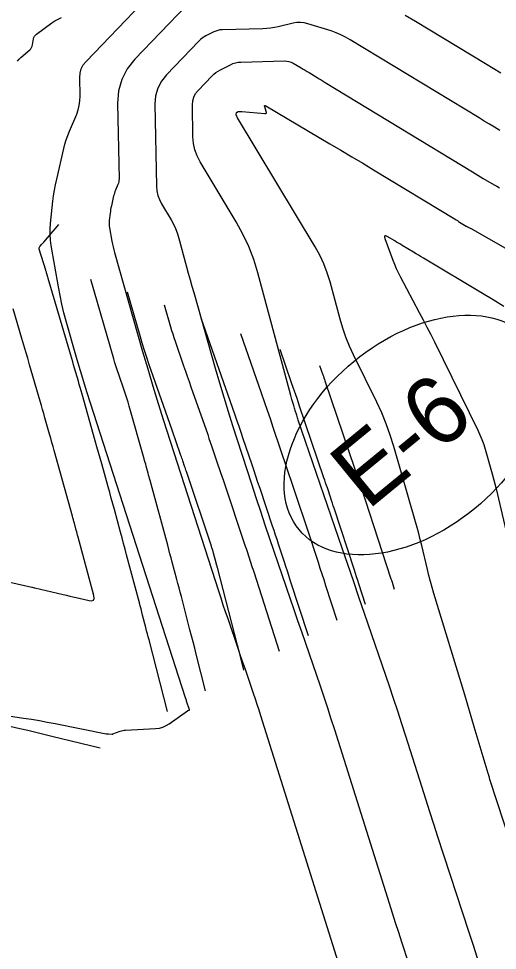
# Model space of a CAD drawing. Extents: x 1005228 to 1008882, y 1883389 to 1885754.
# Drawn here: x 1008220.2 to 1008264.2, y 1884267.3 to 1884352.9 of the extents above; entities that cross this region are included whole.
import ezdxf

# ---------------------------------------------------------------- set-up
doc = ezdxf.new("R2010")
doc.units = 0
for name, color, linetype in [('ATDIMS', 7, 'Continuous'), ('C-ANNO-NOTE', 7, 'Continuous'), ('R_Erosion', 7, 'Continuous'), ('S_BRIDGE', 7, 'Continuous'), ('TSOBSTACLE', 7, 'Continuous')]:
    doc.layers.add(name, color=color, linetype=linetype)

msp = doc.modelspace()

# ---------------------------------------------------------------- linework, layer by layer
at = {"layer": 'ATDIMS'}
for points in [[(1008217.624, 1884301.505), (1008221.421, 1884300.64), (1008221.459, 1884300.631), (1008221.546, 1884300.612), (1008221.646, 1884300.59), (1008221.662, 1884300.587), (1008221.679, 1884300.583), (1008221.695, 1884300.579), (1008221.712, 1884300.575), (1008224.325, 1884299.96), (1008224.621, 1884299.891), (1008224.917, 1884299.822), (1008225.213, 1884299.753), (1008225.508, 1884299.684), (1008226.692, 1884299.41), (1008226.941, 1884299.387), (1008227.097, 1884299.454), (1008227.159, 1884299.612), (1008227.127, 1884299.86), (1008225.689, 1884305.243), (1008225.646, 1884305.402), (1008225.604, 1884305.562), (1008225.561, 1884305.721), (1008225.517, 1884305.881), (1008225.345, 1884306.519), (1008225.301, 1884306.678), (1008225.258, 1884306.838), (1008225.214, 1884306.997), (1008225.169, 1884307.156), (1008223.489, 1884313.184), (1008223.383, 1884313.562), (1008223.277, 1884313.94), (1008223.171, 1884314.317), (1008223.064, 1884314.695), (1008222.637, 1884316.206), (1008222.53, 1884316.583), (1008222.422, 1884316.961), (1008222.314, 1884317.338), (1008222.205, 1884317.715), (1008221.23, 1884321.065), (1008221.055, 1884321.666), (1008220.879, 1884322.267), (1008220.703, 1884322.868), (1008220.526, 1884323.469), (1008219.72, 1884326.205)], [(1008236.97, 1884325.388), (1008240.052, 1884316.574), (1008240.25, 1884316.004), (1008240.448, 1884315.434), (1008240.643, 1884314.863), (1008240.838, 1884314.292), (1008241.613, 1884312.007), (1008241.806, 1884311.436), (1008242, 1884310.864), (1008242.192, 1884310.292), (1008242.384, 1884309.72), (1008243.539, 1884306.279), (1008243.677, 1884305.867), (1008243.814, 1884305.455), (1008243.95, 1884305.043), (1008244.086, 1884304.63), (1008244.626, 1884302.979), (1008244.76, 1884302.566), (1008244.895, 1884302.153), (1008245.029, 1884301.74), (1008245.163, 1884301.327), (1008246.825, 1884296.198)]]:
    msp.add_lwpolyline(points, dxfattribs=at)
at = {"layer": 'C-ANNO-NOTE'}
for points in [[(1008216.682, 1884289.232), (1008220.679, 1884288.624), (1008221.405, 1884288.509), (1008222.13, 1884288.386), (1008222.853, 1884288.254), (1008223.575, 1884288.115), (1008228.269, 1884287.178), (1008228.324, 1884287.169), (1008228.38, 1884287.162), (1008228.435, 1884287.157), (1008228.491, 1884287.155), (1008228.814, 1884287.152), (1008228.84, 1884287.152), (1008228.866, 1884287.152), (1008228.872, 1884287.152), (1008228.878, 1884287.153), (1008228.885, 1884287.155), (1008228.891, 1884287.157), (1008229.567, 1884287.414), (1008229.683, 1884287.453), (1008229.801, 1884287.483), (1008229.92, 1884287.504), (1008230.042, 1884287.515), (1008232.817, 1884287.662), (1008233.155, 1884287.704), (1008233.477, 1884287.79), (1008233.783, 1884287.923), (1008234.072, 1884288.101), (1008235.73, 1884289.282), (1008235.747, 1884289.293), (1008235.765, 1884289.302), (1008235.785, 1884289.309), (1008235.805, 1884289.314), (1008235.887, 1884289.329), (1008235.905, 1884289.334), (1008235.915, 1884289.344), (1008235.919, 1884289.358), (1008235.916, 1884289.376), (1008235.664, 1884290.175), (1008235.66, 1884290.188), (1008235.656, 1884290.201), (1008235.651, 1884290.215), (1008235.647, 1884290.228), (1008235.585, 1884290.408), (1008235.579, 1884290.425), (1008235.574, 1884290.442), (1008235.568, 1884290.459), (1008235.563, 1884290.475), (1008226.535, 1884318.49), (1008226.278, 1884319.298), (1008226.029, 1884320.108), (1008225.786, 1884320.92), (1008225.55, 1884321.734), (1008224.602, 1884325.062), (1008224.389, 1884325.845), (1008224.198, 1884326.633), (1008224.027, 1884327.426), (1008223.878, 1884328.224), (1008223.218, 1884332.014), (1008223.148, 1884332.52), (1008223.114, 1884333.027), (1008223.116, 1884333.535), (1008223.153, 1884334.045), (1008223.377, 1884336.085), (1008223.44, 1884336.594), (1008223.518, 1884337.1), (1008223.612, 1884337.604), (1008223.72, 1884338.105), (1008224.371, 1884340.915), (1008224.475, 1884341.326), (1008224.598, 1884341.732), (1008224.737, 1884342.131), (1008224.894, 1884342.525), (1008225.557, 1884344.09), (1008225.701, 1884344.485), (1008225.801, 1884344.889), (1008225.858, 1884345.301), (1008225.872, 1884345.721), (1008225.84, 1884347.446), (1008225.87, 1884347.86), (1008225.977, 1884348.244), (1008226.16, 1884348.598), (1008226.419, 1884348.923), (1008234.44, 1884357.265)], [(1008235.618, 1884354.034), (1008230.912, 1884349.139), (1008230.199, 1884348.247), (1008229.696, 1884347.272), (1008229.402, 1884346.214), (1008229.319, 1884345.075), (1008229.448, 1884338.143), (1008229.444, 1884338.005), (1008229.425, 1884337.87), (1008229.392, 1884337.738), (1008229.345, 1884337.608), (1008229.128, 1884337.096), (1008229.077, 1884336.967), (1008229.031, 1884336.836), (1008228.991, 1884336.703), (1008228.957, 1884336.569), (1008228.744, 1884335.648), (1008228.708, 1884335.484), (1008228.677, 1884335.319), (1008228.652, 1884335.154), (1008228.631, 1884334.987), (1008228.558, 1884334.319), (1008228.546, 1884334.152), (1008228.545, 1884333.985), (1008228.556, 1884333.819), (1008228.579, 1884333.653), (1008228.795, 1884332.412), (1008228.844, 1884332.151), (1008228.9, 1884331.891), (1008228.963, 1884331.633), (1008229.032, 1884331.377), (1008231.621, 1884322.296), (1008232.083, 1884320.699), (1008232.559, 1884319.107), (1008233.049, 1884317.518), (1008233.552, 1884315.934), (1008238.588, 1884300.307), (1008238.795, 1884299.668), (1008239.006, 1884299.03), (1008239.219, 1884298.393), (1008239.436, 1884297.757), (1008240.394, 1884294.959), (1008240.568, 1884294.452), (1008240.742, 1884293.945), (1008240.916, 1884293.437), (1008241.09, 1884292.93), (1008241.785, 1884290.901), (1008241.958, 1884290.393), (1008242.127, 1884289.885), (1008242.293, 1884289.375), (1008242.456, 1884288.864), (1008251.629, 1884259.753)], [(1008220.119, 1884348.952), (1008220.271, 1884349.119), (1008220.435, 1884349.276), (1008221.25, 1884350.001), (1008221.343, 1884350.098), (1008221.416, 1884350.206), (1008221.469, 1884350.325), (1008221.503, 1884350.455), (1008221.596, 1884350.998), (1008221.63, 1884351.127), (1008221.687, 1884351.242), (1008221.765, 1884351.343), (1008221.866, 1884351.431), (1008223.284, 1884352.459), (1008223.564, 1884352.645), (1008223.855, 1884352.809), (1008224.158, 1884352.949)], [(1008264.549, 1884347.843), (1008263.839, 1884348.269), (1008263.13, 1884348.698), (1008256.701, 1884352.599), (1008255.761, 1884353.132)], [(1008262.504, 1884266.257), (1008262.054, 1884267.635), (1008261.604, 1884269.012), (1008258.755, 1884277.711), (1008258.379, 1884278.863), (1008258.007, 1884280.016), (1008257.638, 1884281.17), (1008257.272, 1884282.325), (1008255.816, 1884286.946), (1008255.448, 1884288.101), (1008255.073, 1884289.252), (1008254.691, 1884290.402), (1008254.302, 1884291.549), (1008252.013, 1884298.228), (1008251.5, 1884299.723), (1008250.988, 1884301.218), (1008250.475, 1884302.713), (1008249.963, 1884304.208), (1008245.929, 1884315.98), (1008245.891, 1884316.091), (1008245.854, 1884316.201), (1008245.818, 1884316.312), (1008245.782, 1884316.423), (1008245.639, 1884316.866), (1008245.603, 1884316.977), (1008245.569, 1884317.089), (1008245.536, 1884317.2), (1008245.503, 1884317.312), (1008245.372, 1884317.773), (1008245.34, 1884317.887), (1008245.308, 1884318.001), (1008245.276, 1884318.115), (1008245.245, 1884318.23), (1008242.209, 1884329.525), (1008241.836, 1884330.743), (1008241.381, 1884331.927), (1008240.844, 1884333.076), (1008240.226, 1884334.19), (1008236.905, 1884339.714), (1008236.625, 1884340.253), (1008236.422, 1884340.815), (1008236.296, 1884341.398), (1008236.246, 1884342.003), (1008236.192, 1884344.926), (1008236.219, 1884345.3), (1008236.316, 1884345.647), (1008236.481, 1884345.967), (1008236.715, 1884346.26), (1008237.975, 1884347.571), (1008238.158, 1884347.745), (1008238.353, 1884347.903), (1008238.56, 1884348.044), (1008238.781, 1884348.168), (1008239.688, 1884348.628), (1008239.918, 1884348.73), (1008240.155, 1884348.804), (1008240.399, 1884348.852), (1008240.65, 1884348.872), (1008244.654, 1884348.973), (1008244.863, 1884348.964), (1008245.065, 1884348.927), (1008245.259, 1884348.861), (1008245.446, 1884348.767), (1008246.179, 1884348.334), (1008246.363, 1884348.225), (1008246.546, 1884348.116), (1008246.728, 1884348.007), (1008246.911, 1884347.897), (1008247.651, 1884347.448), (1008247.836, 1884347.337), (1008248.02, 1884347.225), (1008248.204, 1884347.114), (1008248.388, 1884347.002), (1008261.947, 1884338.773), (1008262.193, 1884338.625), (1008262.44, 1884338.477), (1008262.686, 1884338.33), (1008262.933, 1884338.183), (1008263.923, 1884337.599), (1008264.172, 1884337.456), (1008264.423, 1884337.318)], [(1008266.771, 1884273.092), (1008263.539, 1884282.961), (1008263.525, 1884283.007), (1008263.512, 1884283.053), (1008263.499, 1884283.099), (1008263.488, 1884283.145), (1008263.444, 1884283.331), (1008263.432, 1884283.378), (1008263.42, 1884283.424), (1008263.408, 1884283.47), (1008263.394, 1884283.516), (1008262.106, 1884287.815), (1008261.886, 1884288.546), (1008261.666, 1884289.278), (1008261.444, 1884290.009), (1008261.222, 1884290.74), (1008258.378, 1884300.067), (1008258.217, 1884300.61), (1008258.065, 1884301.155), (1008257.922, 1884301.704), (1008257.788, 1884302.254), (1008257.271, 1884304.461), (1008257.138, 1884305.012), (1008256.999, 1884305.561), (1008256.852, 1884306.108), (1008256.699, 1884306.653), (1008254.712, 1884313.56), (1008254.385, 1884314.608), (1008254.013, 1884315.638), (1008253.596, 1884316.65), (1008253.133, 1884317.645), (1008250.999, 1884321.979), (1008250.629, 1884322.778), (1008250.3, 1884323.592), (1008250.011, 1884324.421), (1008249.762, 1884325.265), (1008248.846, 1884328.671), (1008248.589, 1884329.51), (1008248.275, 1884330.326), (1008247.906, 1884331.118), (1008247.48, 1884331.885), (1008240.354, 1884343.737), (1008240.227, 1884344.025), (1008240.247, 1884344.222), (1008240.415, 1884344.326), (1008240.73, 1884344.338), (1008242.848, 1884344.152), (1008242.938, 1884344.156), (1008242.991, 1884344.188), (1008243.008, 1884344.248), (1008242.989, 1884344.336), (1008242.841, 1884344.741), (1008242.821, 1884344.823), (1008242.832, 1884344.866), (1008242.877, 1884344.87), (1008242.953, 1884344.834), (1008248.824, 1884341.367), (1008249.833, 1884340.77), (1008250.84, 1884340.17), (1008251.846, 1884339.567), (1008252.849, 1884338.961), (1008260.34, 1884334.427), (1008260.445, 1884334.364), (1008260.549, 1884334.301), (1008260.654, 1884334.237), (1008260.758, 1884334.174), (1008261.356, 1884333.811), (1008261.385, 1884333.794), (1008261.413, 1884333.777), (1008261.471, 1884333.743), (1008261.485, 1884333.735), (1008261.5, 1884333.727), (1008261.515, 1884333.719), (1008261.529, 1884333.712), (1008261.776, 1884333.592), (1008261.822, 1884333.569), (1008261.867, 1884333.546), (1008261.912, 1884333.522), (1008261.957, 1884333.497), (1008279.696, 1884323.358)], [(1008264.806, 1884326.427), (1008263.83, 1884327.016), (1008262.852, 1884327.603), (1008257.444, 1884330.842), (1008257.213, 1884330.98), (1008256.983, 1884331.119), (1008256.752, 1884331.258), (1008256.522, 1884331.397), (1008255.484, 1884332.025), (1008255.312, 1884332.129), (1008255.14, 1884332.232), (1008254.968, 1884332.335), (1008254.795, 1884332.437), (1008254.104, 1884332.845), (1008253.961, 1884332.911), (1008253.879, 1884332.904), (1008253.857, 1884332.824), (1008253.896, 1884332.672), (1008254.619, 1884330.688), (1008254.769, 1884330.297), (1008254.933, 1884329.913), (1008255.11, 1884329.534), (1008255.3, 1884329.161), (1008257.049, 1884325.879), (1008257.404, 1884325.208), (1008257.753, 1884324.533), (1008258.096, 1884323.856), (1008258.434, 1884323.176), (1008262.429, 1884315.064), (1008262.628, 1884314.636), (1008262.807, 1884314.201), (1008262.967, 1884313.758), (1008263.108, 1884313.308), (1008263.63, 1884311.492), (1008263.758, 1884311.037), (1008263.88, 1884310.58), (1008263.997, 1884310.123), (1008264.107, 1884309.663), (1008266.588, 1884299.083)]]:
    msp.add_lwpolyline(points, dxfattribs=at)
at = {"layer": 'R_Erosion'}
msp.add_ellipse((1008256.584, 1884314.613), major_axis=(10.591, 8.686), ratio=0.638788, dxfattribs=at)
at = {"layer": 'S_BRIDGE'}
msp.add_lwpolyline([(1008264.453, 1884342.59), (1008263.973, 1884342.874), (1008263.494, 1884343.16), (1008263.016, 1884343.447), (1008262.539, 1884343.736), (1008250.702, 1884350.919), (1008250.279, 1884351.159), (1008249.843, 1884351.373), (1008249.395, 1884351.56), (1008248.936, 1884351.721), (1008246.817, 1884352.393), (1008246.479, 1884352.477), (1008246.139, 1884352.513), (1008245.797, 1884352.501), (1008245.453, 1884352.442), (1008244.076, 1884352.111), (1008243.731, 1884352.037), (1008243.383, 1884351.982), (1008243.032, 1884351.946), (1008242.679, 1884351.927), (1008238.915, 1884351.832), (1008238.716, 1884351.817), (1008238.523, 1884351.779), (1008238.335, 1884351.72), (1008238.153, 1884351.64), (1008237.435, 1884351.275), (1008237.26, 1884351.177), (1008237.096, 1884351.065), (1008236.941, 1884350.941), (1008236.797, 1884350.802), (1008233.814, 1884347.7), (1008233.34, 1884347.107), (1008233.006, 1884346.459), (1008232.811, 1884345.757), (1008232.756, 1884345), (1008232.896, 1884337.462), (1008232.931, 1884337.036), (1008233.02, 1884336.625), (1008233.163, 1884336.23), (1008233.359, 1884335.851), (1008234.254, 1884334.363), (1008234.463, 1884333.985), (1008234.645, 1884333.596), (1008234.8, 1884333.195), (1008234.926, 1884332.781), (1008235.658, 1884330.06), (1008235.818, 1884329.468), (1008235.981, 1884328.875), (1008236.146, 1884328.284), (1008236.313, 1884327.693), (1008238.295, 1884320.74), (1008238.678, 1884319.418), (1008239.072, 1884318.1), (1008239.477, 1884316.785), (1008239.894, 1884315.474), (1008241.613, 1884310.138), (1008242.023, 1884308.877), (1008242.438, 1884307.618), (1008242.859, 1884306.361), (1008243.286, 1884305.106), (1008245.179, 1884299.584), (1008245.522, 1884298.582), (1008245.865, 1884297.581), (1008246.208, 1884296.58), (1008246.551, 1884295.579), (1008247.924, 1884291.574), (1008248.264, 1884290.572), (1008248.598, 1884289.568), (1008248.925, 1884288.561), (1008249.247, 1884287.553), (1008254.271, 1884271.609), (1008254.553, 1884270.72), (1008254.837, 1884269.832), (1008255.123, 1884268.945), (1008255.412, 1884268.059), (1008256.688, 1884264.162)], dxfattribs=at)
at = {"layer": 'TSOBSTACLE'}
for points in [[(1008233.89, 1884289.218), (1008232.209, 1884295.79), (1008232.136, 1884296.075), (1008232.062, 1884296.36), (1008231.989, 1884296.645), (1008231.915, 1884296.93), (1008231.619, 1884298.07), (1008231.545, 1884298.355), (1008231.47, 1884298.639), (1008231.395, 1884298.924), (1008231.32, 1884299.208), (1008230.147, 1884303.595), (1008230.008, 1884304.117), (1008229.868, 1884304.638), (1008229.727, 1884305.16), (1008229.586, 1884305.681), (1008229.022, 1884307.765), (1008228.88, 1884308.286), (1008228.737, 1884308.807), (1008228.594, 1884309.328), (1008228.449, 1884309.848), (1008227.859, 1884311.965), (1008227.712, 1884312.492), (1008227.564, 1884313.018), (1008227.416, 1884313.544), (1008227.268, 1884314.07), (1008226.052, 1884318.371), (1008225.968, 1884318.669), (1008225.883, 1884318.967), (1008225.797, 1884319.264), (1008225.711, 1884319.562), (1008225.365, 1884320.752), (1008225.278, 1884321.049), (1008225.191, 1884321.346), (1008225.104, 1884321.644), (1008225.017, 1884321.941), (1008222.941, 1884328.991), (1008222.923, 1884329.054), (1008222.904, 1884329.118), (1008222.885, 1884329.181), (1008222.866, 1884329.244), (1008222.789, 1884329.498), (1008222.77, 1884329.561), (1008222.751, 1884329.624), (1008222.731, 1884329.688), (1008222.712, 1884329.751), (1008222.119, 1884331.687), (1008222.107, 1884331.751), (1008222.112, 1884331.811), (1008222.132, 1884331.868), (1008222.169, 1884331.922), (1008222.35, 1884332.129), (1008222.44, 1884332.233), (1008222.53, 1884332.337), (1008223.921, 1884333.937)], [(1008237.41, 1884291.117), (1008236.548, 1884294.489), (1008236.404, 1884295.051), (1008236.259, 1884295.612), (1008236.114, 1884296.174), (1008235.969, 1884296.736), (1008235.177, 1884299.786), (1008235.075, 1884300.179), (1008234.972, 1884300.573), (1008234.868, 1884300.966), (1008234.763, 1884301.359), (1008234.343, 1884302.93), (1008234.238, 1884303.323), (1008234.133, 1884303.715), (1008234.027, 1884304.108), (1008233.921, 1884304.5), (1008232.31, 1884310.447), (1008232.265, 1884310.612), (1008232.22, 1884310.778), (1008232.174, 1884310.942), (1008232.129, 1884311.107), (1008231.945, 1884311.767), (1008231.899, 1884311.931), (1008231.853, 1884312.096), (1008231.806, 1884312.261), (1008231.76, 1884312.426), (1008230.39, 1884317.271), (1008230.284, 1884317.636), (1008230.173, 1884318), (1008230.056, 1884318.362), (1008229.933, 1884318.722), (1008229.433, 1884320.16), (1008229.31, 1884320.521), (1008229.192, 1884320.882), (1008229.079, 1884321.246), (1008228.971, 1884321.611), (1008226.862, 1884328.89)], [(1008240.93, 1884293.017), (1008240.575, 1884294.403), (1008240.516, 1884294.634), (1008240.457, 1884294.865), (1008240.397, 1884295.096), (1008240.338, 1884295.326), (1008238.493, 1884302.435), (1008238.484, 1884302.471), (1008238.475, 1884302.507), (1008238.465, 1884302.542), (1008238.456, 1884302.578), (1008238.418, 1884302.721), (1008238.408, 1884302.757), (1008238.398, 1884302.792), (1008238.389, 1884302.828), (1008238.379, 1884302.864), (1008238.134, 1884303.768), (1008238.089, 1884303.931), (1008238.041, 1884304.092), (1008237.991, 1884304.253), (1008237.939, 1884304.413), (1008235.642, 1884311.258), (1008235.601, 1884311.38), (1008235.56, 1884311.502), (1008235.518, 1884311.625), (1008235.477, 1884311.747), (1008235.311, 1884312.235), (1008235.27, 1884312.358), (1008235.228, 1884312.48), (1008235.186, 1884312.601), (1008235.143, 1884312.723), (1008234.669, 1884314.078), (1008234.576, 1884314.345), (1008234.483, 1884314.611), (1008234.39, 1884314.878), (1008234.298, 1884315.144), (1008232.234, 1884321.072), (1008232.01, 1884321.73), (1008231.795, 1884322.39), (1008231.589, 1884323.053), (1008231.391, 1884323.719), (1008230.232, 1884327.723)], [(1008233.601, 1884326.556), (1008234.18, 1884324.556), (1008234.279, 1884324.223), (1008234.382, 1884323.892), (1008234.489, 1884323.562), (1008234.601, 1884323.234), (1008235.386, 1884320.977), (1008235.555, 1884320.492), (1008235.725, 1884320.007), (1008235.894, 1884319.521), (1008236.064, 1884319.036), (1008237.598, 1884314.648), (1008237.718, 1884314.303), (1008237.838, 1884313.957), (1008237.956, 1884313.61), (1008238.075, 1884313.264), (1008238.545, 1884311.877), (1008238.662, 1884311.53), (1008238.78, 1884311.183), (1008238.897, 1884310.836), (1008239.013, 1884310.489), (1008241.058, 1884304.395), (1008241.123, 1884304.2), (1008241.188, 1884304.005), (1008241.253, 1884303.81), (1008241.317, 1884303.614), (1008241.573, 1884302.832), (1008241.637, 1884302.636), (1008241.7, 1884302.441), (1008241.764, 1884302.245), (1008241.827, 1884302.05), (1008244.184, 1884294.773)], [(1008240.61, 1884323.923), (1008242.506, 1884318.499), (1008242.783, 1884317.705), (1008243.057, 1884316.911), (1008243.33, 1884316.116), (1008243.601, 1884315.32), (1008244.913, 1884311.454), (1008245.066, 1884311), (1008245.22, 1884310.545), (1008245.373, 1884310.09), (1008245.526, 1884309.635), (1008246.137, 1884307.816), (1008246.289, 1884307.361), (1008246.44, 1884306.905), (1008246.591, 1884306.45), (1008246.74, 1884305.994), (1008247.744, 1884302.925), (1008247.917, 1884302.395), (1008248.09, 1884301.865), (1008248.262, 1884301.335), (1008248.434, 1884300.804), (1008249.465, 1884297.622)], [(1008252.106, 1884299.047), (1008251.491, 1884300.945), (1008251.388, 1884301.261), (1008251.285, 1884301.577), (1008251.182, 1884301.893), (1008251.079, 1884302.21), (1008249.222, 1884307.887), (1008249.145, 1884308.122), (1008249.068, 1884308.356), (1008248.99, 1884308.59), (1008248.912, 1884308.824), (1008248.598, 1884309.759), (1008248.519, 1884309.992), (1008248.441, 1884310.226), (1008248.362, 1884310.46), (1008248.283, 1884310.693), (1008246.018, 1884317.369), (1008245.845, 1884317.879), (1008245.67, 1884318.389), (1008245.494, 1884318.898), (1008245.316, 1884319.407), (1008244.249, 1884322.459)], [(1008247.889, 1884320.994), (1008248.185, 1884320.149), (1008248.234, 1884320.008), (1008248.282, 1884319.867), (1008248.331, 1884319.726), (1008248.379, 1884319.585), (1008251.653, 1884309.932), (1008251.67, 1884309.882), (1008251.691, 1884309.819), (1008251.699, 1884309.794), (1008251.704, 1884309.781), (1008254.414, 1884301.494), (1008254.447, 1884301.392), (1008254.481, 1884301.29), (1008254.514, 1884301.187), (1008254.547, 1884301.085), (1008254.746, 1884300.471)], [(1008215.868, 1884288.711), (1008220.323, 1884287.673), (1008221.063, 1884287.5), (1008221.803, 1884287.324), (1008222.542, 1884287.147), (1008223.281, 1884286.967), (1008227.712, 1884285.884)]]:
    msp.add_lwpolyline(points, dxfattribs=at)

# ---------------------------------------------------------------- texts
at = {"layer": 'R_Erosion'}
msp.add_text('E-6', height=6.2498, rotation=39.35432, dxfattribs=at).set_placement((1008252.276, 1884307.634))

doc.saveas('drawing.dxf')
